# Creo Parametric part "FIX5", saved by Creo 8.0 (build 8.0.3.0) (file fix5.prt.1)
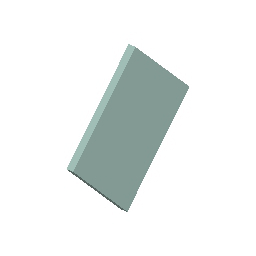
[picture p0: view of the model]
Units: millimeter Newton Second (mmNs); MM, TONNE, SECS

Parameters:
  SMT_DFLT_BEND_REL_LENGTH_TYPE = "Through All"

Other parameters: SMT_THICKNESS, SMT_PART_BEND_ALLOWANCE_FACTOR, SMT_DFLT_BEND_RADIUS, SMT_DFLT_BEND_ANGLE, SMT_DFLT_CRNR_REL_WIDTH, SMT_DFLT_CRNR_REL_DEPTH, SMT_DFLT_BEND_REL_WIDTH, SMT_DFLT_BEND_REL_DEPTH, SMT_DFLT_BEND_REL_LENGTH, SMT_DFLT_BEND_REL_ANGLE, SMT_GAP, SMT_DFLT_EDGE_TREA_WIDTH, SMT_DFLT_MITER_CUT_WIDTH, SMT_DFLT_MITER_CUT_OFFSET

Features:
  1. coordinate system

Other named items: CS0

Layers: 0_ALL_AXIS, 0_ALL_CSYS, 0_ALL_CURVES, 0_ALL_PLANES, 0_ALL_POINTS, 0_ALL_SURFS, FIX5

Surfaces: 6 plane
